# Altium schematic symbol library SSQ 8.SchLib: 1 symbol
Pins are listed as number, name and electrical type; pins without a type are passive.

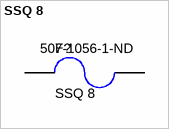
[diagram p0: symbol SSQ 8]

## SSQ 8
designator F?  Supplier Part Number: 507-1056-1-ND
FUSE BRD MNT 8A 125VAC 86VDC SMD; Manufacturer: Bel Fuse Inc; U/M: EA; Response Time: Fast; Fuse Type: Board Mount (Cartridge Style Excluded); Voltage Rating - DC: 86V; Approvals: CE, cULus; DC Cold Resistance: 0.008 Ohm; Voltage Rating - AC: 125V; Melting I²t: 26; Breaking Capacity @ Rated Voltage: 50A AC, 10kA DC
simulation model Fuse (Altium default FUSE subcircuit)
footprint SSQ (BEL FUSE INC SSQ FUSE)
pins: 1, 2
